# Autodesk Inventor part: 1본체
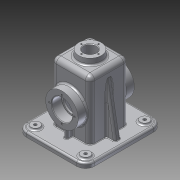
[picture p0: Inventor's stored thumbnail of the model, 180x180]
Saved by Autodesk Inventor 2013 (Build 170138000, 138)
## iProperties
Created: 2016-01
Part Number: 1본체
Material: 알루미늄 6061
Document SubType Name: Modeling
Designer: Administrator
Density: 2.71 g/cm^3
Mass: 849.35 g
Surface Area: 903.523 cm^2
Volume: 313.413 cm^3
Author: Administrator
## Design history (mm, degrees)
sketch "스케치1"
  geometry: L1 (-57.5, 65)-(57.5, 65); L2 (57.5, 65)-(57.5, -65); L3 (57.5, -65)-(-57.5, -65); L4 (-57.5, -65)-(-57.5, 65); 3 further points
  constraints: 8 end point, 2 midpoint, 2 parallel, 1 horizontal, 1 horizontal alignment, 1 perpendicular, 1 vertical alignment
  dimensions: "d0" = 115 distance of L2.end L3.end; "d2" = 130 distance of L1.end L2.end
extrude "돌출1" new body sketch "스케치1" distance "d3" = 8; taper "d4" = 0 deg
sketch "스케치2"
  geometry: L1 (-32.5, 32.5)-(32.5, 32.5); L2 (32.5, 32.5)-(32.5, -32.5); L3 (32.5, -32.5)-(-32.5, -32.5); L4 (-32.5, -32.5)-(-32.5, 32.5); 3 further points
  constraints: 8 end point, 2 midpoint, 2 parallel, 1 horizontal, 1 horizontal alignment, 1 perpendicular, 1 vertical alignment
  dimensions: "d5" = 65 distance of L1.end L2.end; "d7" = 65 distance of L2.end L3.end
extrude "돌출2" join sketch "스케치2" distance "d8" = 100; taper "d9" = 0 deg
fillet "모깎기1" dims "d10" = 15
sketch "스케치3"
  geometry: L1 (-57.5, 50)-(-57.5, -50) reference; L2 (-42.5, -65)-(42.5, -65) reference; L3 (57.5, -50)-(57.5, 50) reference; L4 (42.5, 65)-(-42.5, 65) reference; L5 (-42.5, 60)-(42.5, 60); L6 (52.5, 50)-(52.5, -50); L7 (42.5, -60)-(-42.5, -60); L8 (-52.5, -50)-(-52.5, 50); A1 r 15 centre (-42.5, 50) between (-42.5, 65) and (-57.5, 50) reference; A2 r 15 centre (-42.5, -50) between (-57.5, -50) and (-42.5, -65) reference; A3 r 15 centre (42.5, -50) between (42.5, -65) and (57.5, -50) reference; A4 r 15 centre (42.5, 50) between (57.5, 50) and (42.5, 65) reference; A5 r 10 centre (-42.5, 50) between (-42.5, 60) and (-52.5, 50); A6 r 10 centre (42.5, 50) between (52.5, 50) and (42.5, 60); A7 r 10 centre (42.5, -50) between (42.5, -60) and (52.5, -50); A8 r 10 centre (-42.5, -50) between (-52.5, -50) and (-42.5, -60); 1 further point
  constraints: 8 end point, 8 point on circle, 4 centre point, 7 other
  dimensions: "d11" = 5 distance between parallel lines of L1 L8
extrude "돌출3" join sketch "스케치3" distance "d12" = 2; taper "d13" = 0 deg
sketch "스케치6"
  geometry: C1 r 27.5 at (0, 53); 1 further point
  constraints: 1 centre point, 1 vertical alignment
  dimensions: "d24" = 55 diameter of C1; "d26" = 53 distance of point (0, 0) C1.centre
extrude "돌출6" join sketch "스케치6" stored distance "d27" = 95; taper "d28" = 0 deg
sketch "스케치4"
  geometry: L1 (27.5, 27.5)-(-27.5, 27.5); L2 (-27.5, 27.5)-(-27.5, -27.5); L3 (-27.5, -27.5)-(27.5, -27.5); L4 (27.5, -27.5)-(27.5, 27.5); L5 (27.5, 27.5)-(-27.5, -27.5); L6 (-27.5, 27.5)-(27.5, -27.5); 1 further point
  constraints: 12 end point, 2 midpoint, 2 parallel, 1 horizontal, 1 perpendicular
  dimensions: "d14" = 55 distance of L1.end L2.end; "d16" = 55 distance of L1.start L1.end
extrude "돌출4" cut sketch "스케치4" distance "d17" = 105; taper "d18" = 0 deg
sketch "스케치5"
  geometry: L1 (27.5, -2)-(-27.5, -2) reference; L2 (27.5, -2)-(27.5, 103) reference; L3 (27.5, 103)-(-27.5, 103) reference; L4 (-27.5, -2)-(-27.5, 103) reference; L5 (-32.5, 8)-(32.5, 8) reference; L6 (-27.5, 8)-(-42.5, 8); L7 (-42.5, 8)-(-42.5, 63); L8 (-42.5, 63)-(-27.5, 63); L9 (-27.5, 63)-(-27.5, 8); 1 further point
  constraints: 8 end point, 2 parallel, 2 point on line, 1 horizontal, 1 perpendicular
  dimensions: "d19" = 15 distance of L6.start L6.end; "d21" = 55 distance of L6.end L7.end
extrude "돌출5" join sketch "스케치5" stored distance "d22" = 6; taper "d23" = 0 deg
node "작업 평면1"
sketch "스케치7"
  geometry: C1 r 20 at (0, 0); 1 further point
  constraints: 1 centre point, 1 coincident
  dimensions: "d30" = 40 diameter of C1
extrude "돌출7" join sketch "스케치7" stored distance "d31" = 95; taper "d32" = 0 deg
feature "면 기울기1" dims angle "d104" = 5 deg
sketch "스케치8"
  geometry: C1 r 7.5 at (-42.5, 50); C2 r 7.5 at (42.5, 50); C3 r 7.5 at (42.5, -50); C4 r 7.5 at (-42.5, -50); A1 r 15 centre (42.5, 50) between (57.5, 50) and (42.5, 65) reference; A2 r 15 centre (-42.5, 50) between (-42.5, 65) and (-57.5, 50) reference; A3 r 15 centre (-42.5, -50) between (-57.5, -50) and (-42.5, -65) reference; A4 r 15 centre (42.5, -50) between (42.5, -65) and (57.5, -50) reference; 1 further point
  constraints: 4 centre point, 4 coincident
  dimensions: "d33" = 15 diameter of C1; "d34" = 15 diameter of C2; "d35" = 15 diameter of C3; "d36" = 15 diameter of C4
extrude "돌출8" join sketch "스케치8" distance "d37" = 3; taper "d38" = 0 deg
sketch "스케치9"
  geometry: C1 r 7.5 at (0, 0) reference; C2 r 7.5 at (-85, 0) reference; C3 r 7.5 at (-85, 100) reference; C4 r 7.5 at (0, 100) reference; 5 further points
  constraints: 4 coincident
hole "구멍1" sketch "스케치9" at (-85, 0), (-85, 100), (0, 100), (0, 0) diameter "d39" = 5; stored, may be unused: countersink angle "d43" = 90 deg, drill point angle "d45" = 118 deg; dims "d40" = 6, "d41" = 4, "d42" = 2, "d44" = 8
sketch "스케치10"
  geometry: C1 r 27.5 at (0, 0) reference; C2 r 15 at (0, 0); 1 further point
  constraints: 1 centre point, 1 coincident
  dimensions: "d46" = 30 diameter of C2
extrude "돌출9" cut sketch "스케치10" stored distance "d47" = 3; taper "d48" = 0 deg
sketch "스케치11"
  geometry: C1 r 20 at (0, 0) reference; C2 r 10.5 at (0, 0)
  constraints: 1 centre point, 1 coincident
  dimensions: "d49" = 21 diameter of C2
extrude "돌출10" cut sketch "스케치11" stored distance "d50" = 3; taper "d51" = 0 deg
sketch "스케치12"
  geometry: C1 r 15 at (0, 0) reference; C2 r 27.5 at (0, 0) reference; C3 r 17.5 at (0, 0); 1 further point
  constraints: 1 centre point, 1 coincident
  dimensions: "d53" = 35 diameter of C3
extrude "돌출11" cut sketch "스케치12" distance "d54" = 17; taper "d55" = 0 deg
sketch "스케치13"
  geometry: L1 (-47.5, 8)-(-30.787, 102.783); L2 (52.5, 0)-(52.5, -2) reference; L3 (52.5, -2)-(27.5, -2) reference; L4 (27.5, -2)-(27.5, 103) reference; L5 (27.5, 103)-(10.5, 103) reference; L6 (10.5, 103)-(10.5, 118) reference; L7 (10.5, 118)-(19.125, 118) reference; L8 (19.125, 118)-(20, 108) reference; L9 (20, 108)-(32.5, 108) reference; L10 (32.5, 108)-(32.5, 8) reference; L11 (32.5, 8)-(57.5, 8) reference; L12 (57.5, 8)-(57.5, 0) reference; L13 (57.5, 0)-(52.5, 0) reference; L14 (-52.5, -2)-(-52.5, 0) reference; L15 (-52.5, 0)-(-57.5, 0) reference; L16 (-57.5, 0)-(-57.5, 8) reference; L17 (-57.5, 8)-(-32.5, 8) reference; L18 (-32.5, 8)-(-32.5, 108) reference; L19 (-32.5, 108)-(-20, 108) reference; L20 (-20, 108)-(-19.125, 118) reference; L21 (-19.125, 118)-(-10.5, 118) reference; L22 (-10.5, 118)-(-10.5, 103) reference; L23 (-10.5, 103)-(-27.5, 103) reference; L24 (-27.5, 103)-(-27.5, -2) reference; L25 (-27.5, -2)-(-52.5, -2) reference; 2 further points
  constraints: 2 end point, 1 horizontal alignment, 1 midpoint
  dimensions: "d56" = 10 distance from line of L16 L1.start; "d57" = 10 deg angle of L16 L1
feature "리브1" sketch "스케치13" dims "d58" = 1, "d59" = 10, "d60" = 0, "d61" = 0, "d62" = 1, "d63" = 1
sketch "스케치14"
  geometry: C1 r 10.5 at (0, 0) reference; 1 further point
  constraints: 1 horizontal alignment
  dimensions: "d64" = 14.5 distance of point (-14.5, 0) C1.centre
hole "구멍2" sketch "스케치14" at (-14.5, 0) diameter "d65" = 2.459; stored, may be unused: countersink angle "d69" = 90 deg, drill point angle "d71" = 118 deg; dims "d66" = 7, "d67" = 4, "d68" = 2, "d70" = 9
sketch "스케치15"
  geometry: C1 r 17.5 at (0, 0) reference; 2 further points
  constraints: 1 vertical alignment
  dimensions: "d75" = 21 distance of C1.centre point (0, 21)
hole "구멍3" sketch "스케치15" at (0, 21) diameter "d76" = 3.242; stored, may be unused: countersink angle "d80" = 90 deg, drill point angle "d82" = 118 deg; dims "d77" = 8, "d78" = 4, "d79" = 2, "d81" = 10
fillet "모깎기2" dims "d86" = 8
fillet "모깎기3" dims "d87" = 8
fillet "모깎기4" dims "d88" = 0.3
fillet "모깎기5" dims "d89" = 3
fillet "모깎기6" dims "d90" = 3
fillet "모깎기7" dims "d91" = 3
fillet "모깎기8" dims "d92" = 3
fillet "모깎기9" dims "d93" = 1
fillet "모깎기10" dims "d94" = 3
fillet "모깎기11" dims "d95" = 3
chamfer "모따기1" distance "d96" = 1; stored, may be unused: second distance "d97" = 2, angle "d98" = 45 deg
fillet "모깎기12" dims "d99" = 3
fillet "모깎기13" dims "d100" = 3
sketch "스케치16"
  geometry: L1 (43.625, -18)-(5.375, -18) reference; A1 r 30.5 centre (24.5, 47) between (0, 28.834) and (49, 28.834) reference; 2 further points
  constraints: 1 vertical alignment, 1 other
  dimensions: "d101" = 27 distance from line of point (24.5, 9) L1
feature "엠보싱1" sketch "스케치16" dims "d102" = 0.5, "d103" = 0
node "솔리드1"
mirror "대칭1"
mirror "대칭2"
mirror "대칭3"
pattern_circular "원형 패턴1" dims angle "d73" = 360 deg
pattern_circular "원형 패턴2" dims angle "d84" = 360 deg
mirror "대칭4"
node "투영된 루프1"
node "투영된 루프2"
node "투영된 루프3"
node "투영된 루프4"
node "절단 모서리 투영1"
other parameters: "d29" = 118
